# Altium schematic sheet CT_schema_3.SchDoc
size 276 x 169 mm
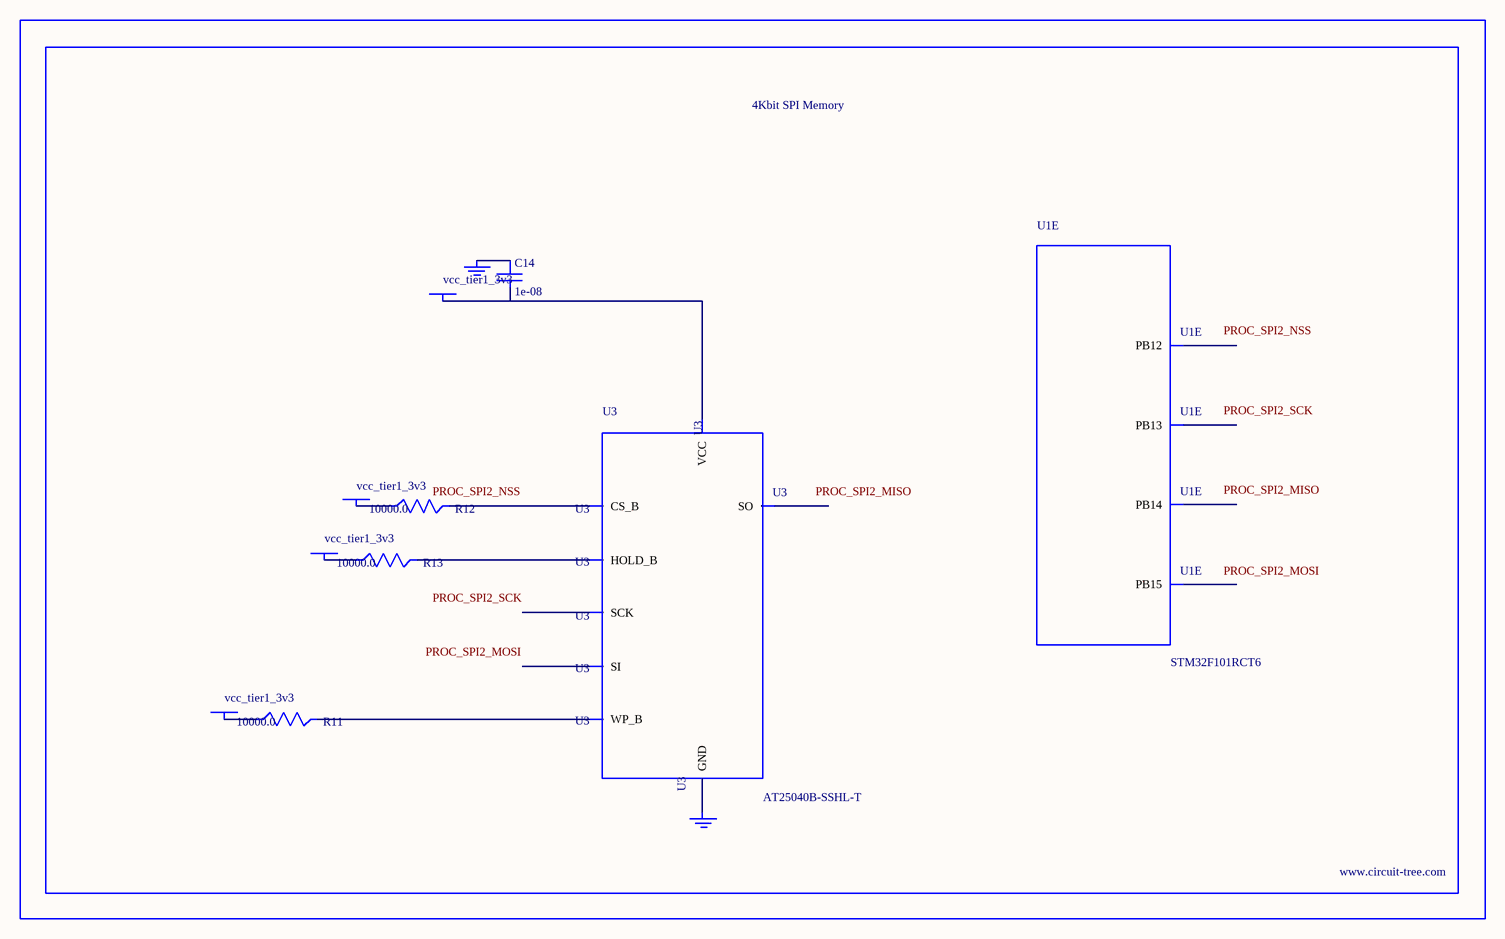
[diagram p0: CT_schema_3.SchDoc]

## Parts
BORDER2  (no value)
C14  1e-08  [C0402]
GND_INSTANCE_2_0  (no value)
GND_INSTANCE_2_1  (no value)
POWER_INSTANCE_2_0  vcc_tier1_3v3
POWER_INSTANCE_2_1  vcc_tier1_3v3
POWER_INSTANCE_2_2  vcc_tier1_3v3
POWER_INSTANCE_2_3  vcc_tier1_3v3
R11  10000.0  [R0603]
R12  10000.0  [R0603]
R13  10000.0  [R0603]
U1  STM32F101RCT6  [LQFP64]  (part E of 7)
U3  AT25040B-SSHL-T  [SOIC-8]

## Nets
NetC14_1: C14.1 GND_INSTANCE_2_0.0(GND)
NetC14_2: C14.2 POWER_INSTANCE_2_3.0(PWR) U3.8(VCC)
NetGND_INSTANCE_2_1_0: GND_INSTANCE_2_1.0(GND) U3.4(GND)
NetPOWER_INSTANCE_2_0_0: POWER_INSTANCE_2_0.0(PWR) R12.1
NetPOWER_INSTANCE_2_1_0: POWER_INSTANCE_2_1.0(PWR) R11.1
NetPOWER_INSTANCE_2_2_0: POWER_INSTANCE_2_2.0(PWR) R13.1
NetR11_2: R11.2 U3.3(WP_B)
NetR12_2: R12.2 U3.1(CS_B)
NetR13_2: R13.2 U3.7(HOLD_B)

Not connected (* = marked no-connect by the designer): U1 33(PB12) 34(PB13) 35(PB14) 36(PB15); U3 2(SO) 5(SI) 6(SCK)

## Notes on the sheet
- Labels drawn without touching a wire or pin: PROC_SPI2_MISO, PROC_SPI2_MOSI, PROC_SPI2_NSS, PROC_SPI2_SCK

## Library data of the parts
BORDER2 = BORDER_PAGE2
C14 = C0402C103K3RAC
GND_INSTANCE_2_0 GND_INSTANCE_2_1 = GND
POWER_INSTANCE_2_0-POWER_INSTANCE_2_3 = PWR
R11-R13 = RC0603JR-0710KL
